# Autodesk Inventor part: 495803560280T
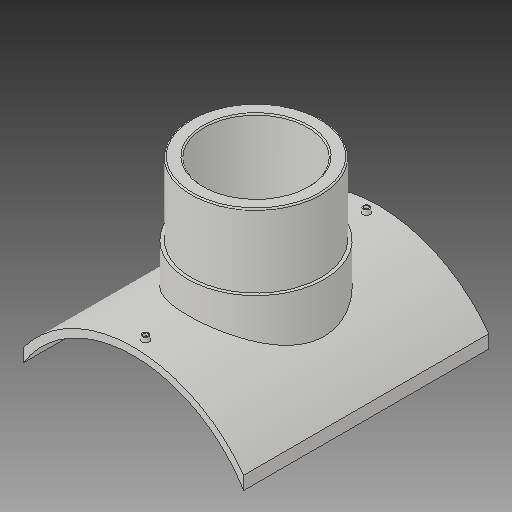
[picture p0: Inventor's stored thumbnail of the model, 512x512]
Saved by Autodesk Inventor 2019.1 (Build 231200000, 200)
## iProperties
Created: 2017-10
Part Number: 495803560280T
Material: Generic
Description: PLASSON BRANCH SADDLE  560x280
Document SubType Name: Modeling
Designer: KIM
Mass: 2754.05 g
Surface Area: 3037.44 cm^2
Volume: 2754.05 cm^3
Density: 1 g/cm^3
Appearance: Default
Author: KIM
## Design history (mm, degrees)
derived "495803.ipt"
feature "Solid1::495803.ipt"
tag "TaggingFeature1"
body "Solid1"
other parameters: "d1" = 16, "d2" = 477, "d4" = 0, "d12" = 305.6, "d13" = 14, "d14" = 238.5, "d16" = 5 deg, "d18" = 4, "d19" = 14, "d20" = 0, "d21" = 3, "d22" = 0, "d23" = 521, "d24" = 294, "d25" = 16, "d26" = 224, "d28" = 0, "d29" = 9.6, "d31" = 0, "d32" = 112.5, "d33" = 0, "d34" = 5.6, "d37" = 157.5, "d38" = 0, "d39" = 2.8, "B_" = 477, "H_" = 225, "x_" = 16, "D_" = 16
